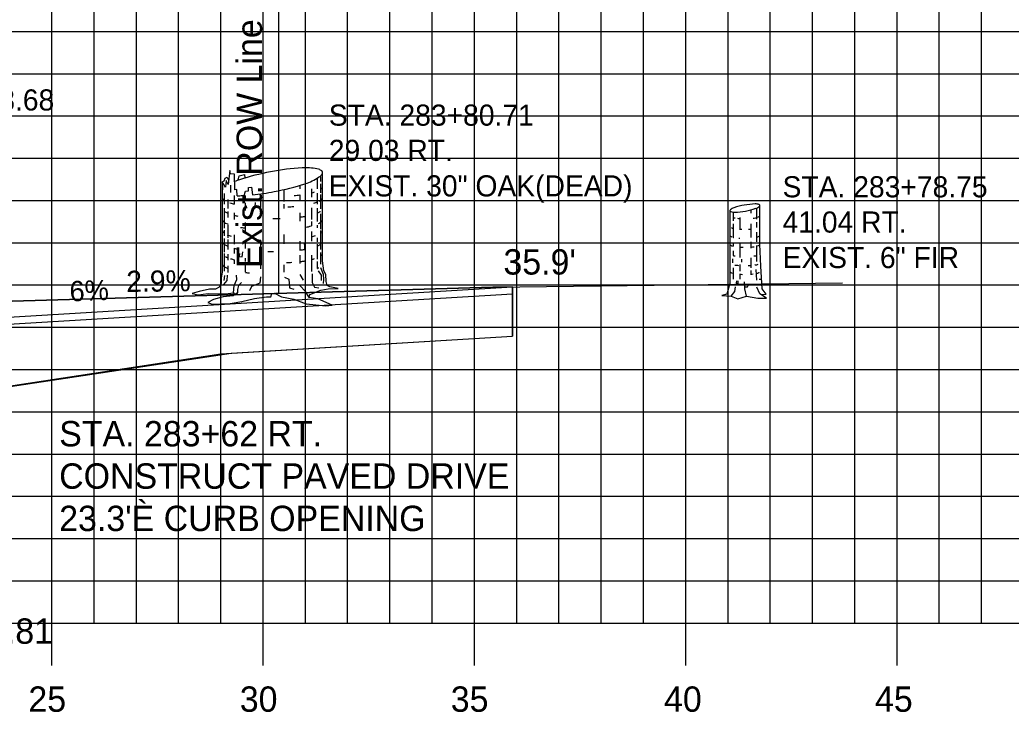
# Model space of a CAD drawing. Extents: x 856235 to 856405, y 366268 to 366378.
# Drawn here: x 856342.02 to 856365.48, y 366298.78 to 366315.17 of the extents above; entities that cross this region are included whole.
import ezdxf

# ---------------------------------------------------------------- set-up
doc = ezdxf.new("R2010")
doc.units = 0
for name, color, linetype in [('ANNOTATION', 7, 'Continuous'), ('D_Roadway_Drive_Gravel_RT', 7, 'Continuous'), ('D_Roadway_Drive_SubGrade', 7, 'Continuous'), ('D_Roadway_FinishedGrade', 7, 'Continuous'), ('D_Text_Monospaced', 7, 'Continuous'), ('D_Text_Standard', 7, 'Continuous'), ('E_ROW_Line', 7, 'Continuous'), ('H_V ANNOTATION', 7, 'Continuous'), ('JUNK COM EXC', 7, 'Continuous'), ('MAJOR', 7, 'Continuous'), ('MINOR', 7, 'Continuous'), ('S_Roadway_Centerline', 7, 'Continuous'), ('S_Trees_Conifer_NonPay', 7, 'Continuous'), ('S_Trees_Decid_Pay', 7, 'Continuous')]:
    doc.layers.add(name, color=color, linetype=linetype)

msp = doc.modelspace()

# ---------------------------------------------------------------- linework, layer by layer
at = {"layer": 'D_Roadway_Drive_Gravel_RT'}
for p, q in [((856340.78, 366308.074), (856353.683, 366308.849)), ((856340.79, 366307.908), (856353.683, 366308.682))]:
    msp.add_line(p, q, dxfattribs=at)
at = {"layer": 'D_Roadway_Drive_SubGrade'}
for p, q in [((856353.683, 366308.849), (856353.683, 366307.682)), ((856335.78, 366305.586), (856346.781, 366307.266))]:
    msp.add_line(p, q, dxfattribs=at)
at = {"layer": 'D_Roadway_FinishedGrade'}
msp.add_line((856346.781, 366307.266), (856353.683, 366307.68), dxfattribs=at)
at = {"layer": 'E_ROW_Line'}
msp.add_line((856348.153, 366308.696), (856348.153, 366318.696), dxfattribs=at)
at = {"layer": 'JUNK COM EXC'}
msp.add_lwpolyline([(856335.781, 366308.158), (856335.781, 366305.586), (856347.021, 366307.28), (856353.683, 366307.68), (856353.683, 366308.849), (856353.214, 366308.843), (856341.841, 366308.513), (856336.902, 366308.157), (856335.781, 366308.158)], dxfattribs=at)
at = {"layer": 'MAJOR'}
for p, q in [((856342.781, 366300.893), (856342.781, 366315.893)), ((856347.781, 366300.893), (856347.781, 366315.893)), ((856352.781, 366300.893), (856352.781, 366315.893)), ((856357.781, 366300.893), (856357.781, 366315.893)), ((856362.781, 366300.893), (856362.781, 366315.893)), ((856247.781, 366310.893), (856387.781, 366310.893)), ((856247.781, 366305.893), (856387.781, 366305.893)), ((856247.781, 366300.893), (856387.781, 366300.893)), ((856247.781, 366300.893), (856387.781, 366300.893)), ((856342.781, 366299.891), (856342.781, 366300.893)), ((856347.781, 366299.891), (856347.781, 366300.893)), ((856352.781, 366299.891), (856352.781, 366300.893)), ((856357.781, 366299.891), (856357.781, 366300.893)), ((856362.781, 366299.891), (856362.781, 366300.893))]:
    msp.add_line(p, q, dxfattribs=at)
at = {"layer": 'MINOR'}
for p, q in [((856343.781, 366300.893), (856343.781, 366315.893)), ((856344.781, 366300.893), (856344.781, 366315.893)), ((856345.781, 366300.893), (856345.781, 366315.893)), ((856346.781, 366300.893), (856346.781, 366315.893)), ((856348.781, 366300.893), (856348.781, 366315.893)), ((856349.781, 366300.893), (856349.781, 366315.893)), ((856350.781, 366300.893), (856350.781, 366315.893)), ((856351.781, 366300.893), (856351.781, 366315.893)), ((856353.781, 366300.893), (856353.781, 366315.893)), ((856354.781, 366300.893), (856354.781, 366315.893)), ((856355.781, 366300.893), (856355.781, 366315.893)), ((856356.781, 366300.893), (856356.781, 366315.893)), ((856358.781, 366300.893), (856358.781, 366315.893)), ((856359.781, 366300.893), (856359.781, 366315.893)), ((856360.781, 366300.893), (856360.781, 366315.893)), ((856361.781, 366300.893), (856361.781, 366315.893)), ((856363.781, 366300.893), (856363.781, 366315.893)), ((856364.781, 366300.893), (856364.781, 366315.893)), ((856247.781, 366314.893), (856387.781, 366314.893)), ((856247.781, 366313.893), (856387.781, 366313.893)), ((856247.781, 366312.893), (856387.781, 366312.893)), ((856247.781, 366311.893), (856387.781, 366311.893)), ((856247.781, 366309.893), (856387.781, 366309.893)), ((856247.781, 366308.893), (856387.781, 366308.893)), ((856247.781, 366307.893), (856387.781, 366307.893)), ((856247.781, 366306.893), (856387.781, 366306.893)), ((856247.781, 366304.893), (856387.781, 366304.893)), ((856247.781, 366303.893), (856387.781, 366303.893)), ((856247.781, 366302.893), (856387.781, 366302.893)), ((856247.781, 366301.893), (856387.781, 366301.893))]:
    msp.add_line(p, q, dxfattribs=at)
at = {"layer": 'S_Roadway_Centerline'}
msp.add_lwpolyline([(856288.766, 366307.134), (856291.997, 366307.346), (856293.116, 366307.459), (856296.849, 366307.753), (856299.153, 366307.782), (856300.226, 366307.769), (856300.611, 366307.582), (856300.668, 366307.591), (856300.837, 366307.587), (856302.732, 366307.68), (856307.504, 366307.852), (856314.412, 366308.118), (856317.731, 366308.235), (856325.349, 366308.101), (856328.588, 366308.036), (856330.64, 366308.017), (856333.315, 366308.002), (856333.411, 366308.015), (856334.63, 366308.158), (856336.902, 366308.157), (856341.841, 366308.513), (856353.214, 366308.843), (856361.49, 366308.945)], dxfattribs=at)
at = {"layer": 'S_Trees_Conifer_NonPay'}
for p, q in [((856358.903, 366310.616), (856358.903, 366310.411)), ((856359.321, 366310.671), (856359.321, 366310.593)), ((856358.903, 366310.338), (856358.903, 366310.007)), ((856359.06, 366310.491), (856359.06, 366310.218)), ((856359.321, 366310.343), (856359.321, 366310.018)), ((856359.456, 366310.383), (856359.456, 366310.252)), ((856359.456, 366310.143), (856359.456, 366309.917)), ((856358.903, 366309.892), (856358.903, 366309.814)), ((856359.06, 366309.864), (856359.06, 366309.546)), ((856359.321, 366309.917), (856359.321, 366309.763)), ((856359.456, 366309.825), (856359.456, 366309.449)), ((856358.903, 366309.7), (856358.903, 366309.59)), ((856358.886, 366309.512), (856358.886, 366309.415)), ((856359.06, 366309.376), (856359.06, 366309.217)), ((856359.101, 366309.501), (856359.101, 366309.432)), ((856359.321, 366309.535), (856359.321, 366309.301)), ((856358.903, 366309.301), (856358.903, 366309.033)), ((856359.06, 366309.159), (856359.06, 366309.028)), ((856359.321, 366309.239), (856359.321, 366309.153)), ((856359.437, 366309.256), (856359.455, 366309.011)), ((856359.516, 366309.028), (856359.577, 366309.034))]:
    msp.add_line(p, q, dxfattribs=at)
for points in [[(856359.567, 366308.667), (856359.683, 366308.676), (856359.591, 366308.801), (856359.558, 366309.342), (856359.537, 366309.859), (856359.537, 366310.778)], [(856358.824, 366310.65), (856358.824, 366308.932), (856358.754, 366308.676), (856358.635, 366308.642), (856358.852, 366308.625), (856359.011, 366308.567), (856359.22, 366308.625), (856359.483, 366308.578), (856359.689, 366308.584), (856359.537, 366308.687), (856359.466, 366308.841)], [(856359.456, 366310.712), (856359.456, 366310.615), (856359.456, 366310.45)], [(856358.983, 366308.988), (856358.972, 366308.944), (856359.022, 366308.932), (856359.022, 366308.994)], [(856359.22, 366308.625), (856359.176, 366308.801), (856359.17, 366308.966)], [(856359.174, 366308.851), (856359.243, 366308.846), (856359.262, 366308.898)], [(856358.852, 366308.625), (856358.941, 366308.738), (856358.958, 366308.852)]]:
    msp.add_lwpolyline(points, dxfattribs=at)
for centre, radius, start, end in [((856359.496, 366308.988), 1.825, 100.3798, 108.3946), ((856359.496, 366308.988), 1.825, 92.3651, 100.3798), ((856359.431, 366310.567), 0.245, 70.3798, 92.3651), ((856359.363, 366310.939), 0.245, 288.3946, 310.3798), ((856359.489, 366310.729), 0.0729, 59.1402, 70.3798), ((856359.475, 366310.808), 0.0729, 310.3798, 321.6195), ((856359.513, 366310.769), 0.0263, 40.3798, 59.1402), ((856359.511, 366310.779), 0.0263, 321.6195, 340.3798), ((856359.519, 366310.774), 0.0186, 26.433, 40.3798), ((856359.523, 366310.776), 0.0141, 10.3798, 26.433), ((856359.518, 366310.776), 0.0186, 340.3798, 354.3267), ((856359.523, 366310.776), 0.0141, 354.3267, 10.3798), ((856358.842, 366310.65), 0.0186, 160.3798, 174.3267), ((856358.838, 366310.65), 0.0141, 174.3267, 190.3798), ((856358.838, 366310.65), 0.0141, 190.3798, 206.433), ((856358.839, 366310.535), 0.0143, 180, 196.0515), ((856358.85, 366310.647), 0.0263, 141.6195, 160.3798), ((856358.842, 366310.652), 0.0186, 206.433, 220.3798), ((856358.848, 366310.657), 0.0263, 220.3798, 239.1402), ((856358.886, 366310.618), 0.0729, 130.3798, 141.6195), ((856358.872, 366310.697), 0.0729, 239.1402, 250.3798), ((856358.998, 366310.487), 0.245, 108.3946, 130.3798), ((856358.93, 366310.86), 0.245, 250.3798, 272.3651), ((856358.864, 366312.439), 1.825, 272.3651, 280.3798), ((856358.864, 366312.439), 1.825, 280.3798, 288.3946), ((856359.396, 366310.723), 0.245, 291.7653, 300), ((856359.481, 366310.575), 0.0738, 300, 311.2506), ((856359.512, 366310.54), 0.0267, 311.2506, 330), ((856359.519, 366310.536), 0.0189, 330, 343.9485), ((856358.966, 366310.723), 0.245, 254.8461, 261.8968), ((856359.181, 366312.231), 1.767, 261.8968, 262.605), ((856359.181, 366312.231), 1.767, 264.3267, 266.0499), ((856359.181, 366312.231), 1.767, 276.2449, 278.1032), ((856359.396, 366310.723), 0.245, 278.1032, 284.1859), ((856359.514, 366310.288), 0.0267, 311.2506, 330), ((856359.521, 366310.284), 0.0189, 330, 343.9485), ((856358.839, 366310.069), 0.0143, 180, 196.0515), ((856358.843, 366310.07), 0.0189, 196.0515, 210), ((856358.85, 366310.074), 0.0267, 210, 228.7494), ((856358.881, 366310.109), 0.0738, 228.7494, 240), ((856358.966, 366310.257), 0.245, 240, 246.7914), ((856358.968, 366310.471), 0.245, 244.3148, 257.5375), ((856359.183, 366311.978), 1.767, 265.8991, 267.5962), ((856359.183, 366311.978), 1.767, 272.7221, 274.4847), ((856359.396, 366310.257), 0.245, 284.1859, 300), ((856359.481, 366310.109), 0.0738, 300, 311.2506), ((856359.512, 366310.074), 0.0267, 311.2506, 330), ((856359.519, 366310.07), 0.0189, 330, 343.9485), ((856358.839, 366309.857), 0.0143, 180, 196.0515), ((856358.843, 366309.858), 0.0189, 196.0515, 210), ((856358.85, 366309.862), 0.0267, 210, 228.7494), ((856358.881, 366309.898), 0.0738, 228.7494, 240), ((856358.967, 366310.046), 0.245, 240, 254.9514), ((856358.966, 366310.257), 0.245, 254.8461, 257.5454), ((856359.181, 366311.765), 1.767, 265.2285, 266.1325), ((856359.181, 366311.553), 1.767, 274.5361, 277.0026), ((856359.396, 366310.046), 0.245, 292.1924, 300), ((856359.481, 366309.898), 0.0738, 300, 311.2506), ((856359.512, 366309.862), 0.0267, 311.2506, 330), ((856359.519, 366309.858), 0.0189, 330, 343.9485), ((856358.966, 366309.826), 0.245, 254.9814, 261.8968), ((856359.18, 366311.334), 1.767, 261.8968, 262.45), ((856359.181, 366311.553), 1.767, 266.0429, 268.5525), ((856359.18, 366311.334), 1.767, 276.7966, 278.1032), ((856359.395, 366309.826), 0.245, 278.1032, 284.3207), ((856358.838, 366309.421), 0.0143, 180, 196.0515), ((856359.18, 366311.117), 1.767, 262.2622, 265.0496), ((856359.18, 366311.117), 1.767, 272.6293, 274.5612), ((856359.18, 366311.117), 1.767, 277.63, 278.1032), ((856359.395, 366309.609), 0.245, 278.1032, 294.6056), ((856358.838, 366309.215), 0.0143, 180, 196.0515), ((856358.842, 366309.216), 0.0189, 196.0515, 210), ((856358.849, 366309.22), 0.0267, 210, 228.7494), ((856358.88, 366309.256), 0.0738, 228.7494, 240), ((856358.965, 366309.403), 0.245, 240, 249.1675), ((856359.18, 366310.911), 1.767, 266.0862, 268.2187), ((856359.18, 366310.911), 1.767, 274.2776, 276.3006), ((856359.395, 366309.403), 0.245, 284.0684, 300), ((856359.48, 366309.256), 0.0738, 300, 302.05)]:
    msp.add_arc(centre, radius, start, end, dxfattribs=at)
at = {"layer": 'S_Trees_Decid_Pay'}
for p, q in [((856349.137, 366311.463), (856349.137, 366311.342)), ((856347.012, 366311.259), (856347.012, 366311.085)), ((856348.652, 366311.252), (856348.652, 366311.165)), ((856349.056, 366311.418), (856349.056, 366311.165)), ((856349.137, 366311.29), (856349.137, 366311.076)), ((856346.862, 366311.059), (856346.862, 366310.805)), ((856347.097, 366311.011), (856347.097, 366310.806)), ((856347.358, 366311.013), (856347.358, 366310.893)), ((856348.268, 366311.151), (856348.268, 366310.87)), ((856348.652, 366311.024), (856348.652, 366310.885)), ((856348.924, 366311.165), (856348.924, 366310.973)), ((856349.056, 366311.069), (856349.056, 366310.805)), ((856349.137, 366311.031), (856349.137, 366310.693)), ((856346.948, 366310.914), (856346.948, 366310.702)), ((856347.358, 366310.841), (856347.358, 366310.656)), ((856347.596, 366310.741), (856347.601, 366310.848)), ((856347.722, 366310.914), (856347.722, 366310.734)), ((856348.268, 366310.805), (856348.268, 366310.702)), ((856346.862, 366310.708), (856346.862, 366310.238)), ((856346.948, 366310.636), (856346.948, 366310.488)), ((856347.097, 366310.599), (856347.097, 366310.445)), ((856348.652, 366310.599), (856348.652, 366310.407)), ((856348.924, 366310.722), (856348.924, 366310.445)), ((856349.056, 366310.708), (856349.056, 366310.399)), ((856349.137, 366310.576), (856349.137, 366310.216)), ((856346.948, 366310.311), (856346.948, 366310.01)), ((856347.358, 366310.37), (856347.358, 366310.142)), ((856348.924, 366310.399), (856348.924, 366310.29)), ((856349.056, 366310.311), (856349.056, 366310.244)), ((856346.862, 366310.187), (856346.862, 366310.053)), ((856347.097, 366310.082), (856347.097, 366309.862)), ((856348.268, 366310.09), (856348.268, 366309.87)), ((856348.924, 366310.156), (856348.924, 366309.927)), ((856349.137, 366310.179), (856349.137, 366309.73)), ((856346.862, 366309.996), (856346.862, 366309.67)), ((856346.948, 366309.973), (856346.948, 366309.73)), ((856347.358, 366309.944), (856347.358, 366309.759)), ((856347.722, 366309.956), (856347.722, 366309.759)), ((856348.652, 366309.927), (856348.652, 366309.719)), ((856349.056, 366310.01), (856349.056, 366309.913)), ((856349.056, 366309.862), (856349.056, 366309.502)), ((856346.862, 366309.641), (856346.862, 366309.221)), ((856346.948, 366309.619), (856346.948, 366309.479)), ((856347.097, 366309.762), (856347.097, 366309.641)), ((856348.652, 366309.598), (856348.652, 366309.399)), ((856348.924, 366309.598), (856348.924, 366309.215)), ((856349.137, 366309.664), (856349.137, 366309.382)), ((856346.948, 366309.347), (856346.948, 366309.191)), ((856347.097, 366309.49), (856347.097, 366309.392)), ((856347.358, 366309.524), (856347.358, 366309.447)), ((856347.358, 366309.37), (856347.358, 366309.196)), ((856347.722, 366309.376), (856347.722, 366309.273)), ((856348.268, 366309.37), (856348.268, 366309.196)), ((856349.056, 366309.45), (856349.056, 366309.283)), ((856346.866, 366309.118), (856346.851, 366309.001)), ((856348.647, 366309.141), (856348.727, 366309.009))]:
    msp.add_line(p, q, dxfattribs=at)
for points in [[(856346.812, 366311.334), (856346.812, 366309.196), (856346.791, 366309.055), (856346.785, 366308.929), (856346.742, 366308.842), (856346.65, 366308.793), (856346.514, 366308.793), (856346.27, 366308.737), (856346.104, 366308.688), (856346.246, 366308.657), (856346.483, 366308.695), (856346.693, 366308.682), (856346.954, 366308.688), (856347.078, 366308.706), (856347.108, 366308.664), (856347.171, 366308.706), (856347.072, 366308.639), (856346.837, 366308.614), (856346.606, 366308.552), (856346.476, 366308.482), (856346.576, 366308.439), (856346.997, 366308.458), (856347.276, 366308.501), (856347.574, 366308.577), (856347.86, 366308.614), (856347.965, 366308.614), (856347.984, 366308.695), (856348.052, 366308.7), (856348.219, 366308.614), (856348.505, 366308.558), (856348.803, 366308.451), (856349.263, 366308.402), (856349.417, 366308.414), (856349.075, 366308.565), (856348.871, 366308.595), (856348.883, 366308.67), (856349.143, 366308.769), (856349.318, 366308.8), (856349.559, 366308.811), (856349.361, 366308.849), (856349.299, 366308.885), (856349.275, 366308.972), (856349.263, 366309.141), (856349.217, 366309.227), (856349.189, 366309.468), (856349.189, 366311.554)], [(856347.168, 366311.006), (856347.16, 366311.151), (856347.115, 366311.143), (856347.1, 366311.517), (856347.006, 366311.525), (856346.992, 366311.605), (856346.954, 366311.268), (856346.909, 366311.362), (856346.888, 366311.208), (856346.812, 366311.334), (856346.818, 366311.144)], [(856346.812, 366311.334), (856346.858, 366311.357), (856346.88, 366311.422), (856346.932, 366311.445), (856346.965, 366311.37)], [(856347.19, 366311.372), (856347.211, 366311.48), (856347.343, 366311.511), (856347.35, 366311.423)], [(856347.329, 366311.011), (856347.366, 366311.114), (856347.432, 366311.12), (856347.432, 366311.202), (856347.506, 366311.208), (856347.531, 366311.028)], [(856348.765, 366309.733), (856348.764, 366309.81), (856348.756, 366309.876)], [(856347.22, 366309.641), (856347.211, 366309.567), (856347.285, 366309.561), (856347.3, 366309.678)], [(856346.932, 366309.126), (856346.925, 366309.001), (856346.843, 366308.906)], [(856347.078, 366308.706), (856347.097, 366308.885), (856347.158, 366309.022), (856347.152, 366309.122)], [(856347.721, 366309.09), (856347.703, 366308.935), (856347.506, 366308.855), (856347.461, 366308.752)], [(856348.941, 366309.155), (856348.941, 366308.95), (856348.999, 366308.84), (856349.096, 366308.824)], [(856349.081, 366309.229), (856349.153, 366309.126), (856349.153, 366309.001)], [(856349.138, 366309.31), (856349.199, 366309.149), (856349.213, 366309.024), (856349.205, 366308.927)], [(856347.269, 366308.954), (856347.195, 366308.885), (856347.177, 366308.787), (856347.171, 366308.706)], [(856348.286, 366309.081), (856348.389, 366309.03), (856348.404, 366308.824), (856348.507, 366308.795)], [(856348.871, 366308.595), (856348.785, 366308.737), (856348.653, 366308.88)]]:
    msp.add_lwpolyline(points, dxfattribs=at)
for centre, radius, start, end in [((856348.791, 366310.369), 1.299, 78.2779, 93.6944), ((856349.102, 366305.553), 6.126, 100.7779, 107.8613), ((856349.102, 366305.553), 6.126, 93.6944, 100.7779), ((856348.38, 366312.528), 1.299, 287.8613, 303.2779), ((856348.957, 366311.172), 0.48, 69.9843, 78.2779), ((856348.83, 366311.842), 0.48, 303.2779, 311.5714), ((856349.065, 366311.468), 0.164, 55.7779, 69.9843), ((856349.039, 366311.606), 0.164, 311.5714, 325.7779), ((856349.097, 366311.515), 0.107, 45.9547, 55.7779), ((856349.127, 366311.546), 0.0645, 33.2779, 45.9547), ((856349.086, 366311.574), 0.107, 325.7779, 335.6011), ((856349.135, 366311.551), 0.0544, 22.46, 33.2779), ((856349.125, 366311.556), 0.0645, 335.6011, 348.2779), ((856349.142, 366311.554), 0.0467, 10.7779, 22.46), ((856349.142, 366311.554), 0.0467, 359.0957, 10.7779), ((856349.135, 366311.554), 0.0544, 348.2779, 359.0957), ((856347.621, 366310.146), 1.299, 107.8613, 113.3069), ((856346.899, 366317.121), 6.126, 280.7779, 287.8613), ((856349.125, 366311.232), 0.0657, 324.8263, 337.5), ((856349.135, 366311.228), 0.0554, 337.5, 348.3185), ((856346.86, 366310.965), 0.0476, 180, 191.6815), ((856347.21, 366312.305), 1.299, 268.1289, 273.6944), ((856346.899, 366317.121), 6.126, 273.6944, 274.0246), ((856346.899, 366317.121), 6.126, 275.9147, 280.7779), ((856348.002, 366316.904), 5.916, 274.9515, 276.3087), ((856348.577, 366312.316), 1.292, 285.5651, 289.0916), ((856349.049, 366311.297), 0.166, 301.67, 315), ((856349.09, 366311.257), 0.109, 315, 324.8263), ((856346.867, 366310.967), 0.0554, 191.6815, 202.5), ((856346.877, 366310.971), 0.0657, 202.5, 215.1737), ((856346.912, 366310.996), 0.109, 215.1737, 225), ((856346.953, 366311.036), 0.166, 225, 239.1924), ((856347.425, 366312.056), 1.292, 250.6119, 255.2856), ((856348.001, 366316.644), 5.916, 266.0776, 267.3043), ((856348.001, 366316.644), 5.916, 273.5382, 274.8924), ((856348.576, 366312.056), 1.292, 288.0829, 292.5), ((856348.886, 366311.309), 0.484, 297.4162, 300.8076), ((856349.048, 366311.036), 0.166, 300.8076, 315), ((856349.089, 366310.996), 0.109, 315, 324.8263), ((856349.124, 366310.971), 0.0657, 324.8263, 337.5), ((856349.134, 366310.967), 0.0554, 337.5, 348.3185), ((856346.953, 366310.773), 0.166, 237.0378, 239.1924), ((856347.116, 366311.046), 0.484, 239.1924, 247.5), ((856347.425, 366311.792), 1.292, 247.5, 248.3537), ((856347.425, 366311.792), 1.292, 255.2856, 259.2632), ((856348.001, 366316.38), 5.916, 276.3184, 277.1546), ((856348.576, 366311.792), 1.292, 277.1546, 278.3662), ((856348.576, 366311.792), 1.292, 291.8071, 292.5), ((856348.886, 366311.046), 0.484, 292.5, 300.8076), ((856349.048, 366310.773), 0.166, 300.8076, 301.6001), ((856346.86, 366310.444), 0.0476, 180, 191.6815), ((856346.867, 366310.446), 0.0554, 191.6815, 202.5), ((856346.877, 366310.45), 0.0657, 202.5, 215.1737), ((856346.912, 366310.475), 0.109, 215.1737, 225), ((856346.953, 366310.515), 0.166, 225, 239.1924), ((856347.116, 366310.788), 0.484, 239.1924, 245.7725), ((856347.425, 366311.535), 1.292, 247.5, 248.4842), ((856348.001, 366316.38), 5.916, 270.1162, 271.7708), ((856348.576, 366311.535), 1.292, 279.2565, 285.6105), ((856348.886, 366310.788), 0.484, 294.6372, 300.8076), ((856349.048, 366310.515), 0.166, 300.8076, 315), ((856349.089, 366310.475), 0.109, 315, 324.8263), ((856349.124, 366310.45), 0.0657, 324.8263, 337.5), ((856349.134, 366310.446), 0.0554, 337.5, 348.3185), ((856346.86, 366310.187), 0.0476, 180, 191.6815), ((856346.867, 366310.189), 0.0554, 191.6815, 202.5), ((856346.877, 366310.192), 0.0657, 202.5, 215.1737), ((856346.912, 366310.217), 0.109, 215.1737, 225), ((856346.953, 366310.258), 0.166, 225, 239.1924), ((856347.425, 366311.277), 1.292, 247.5, 251.799), ((856347.425, 366311.535), 1.292, 261.8726, 262.8454), ((856348.001, 366316.123), 5.916, 262.8454, 263.7595), ((856348.576, 366311.277), 1.292, 285.6105, 290.1001), ((856349.048, 366310.258), 0.166, 302.0694, 315), ((856349.089, 366310.217), 0.109, 315, 324.8263), ((856349.124, 366310.192), 0.0657, 324.8263, 337.5), ((856349.134, 366310.189), 0.0554, 337.5, 348.3185), ((856346.86, 366309.921), 0.0476, 180, 191.6815), ((856346.867, 366309.923), 0.0554, 191.6815, 202.5), ((856346.877, 366309.927), 0.0657, 202.5, 215.1737), ((856346.912, 366309.952), 0.109, 215.1737, 225), ((856346.953, 366309.992), 0.166, 225, 239.1924), ((856347.116, 366310.265), 0.484, 239.1924, 247.5), ((856347.425, 366311.012), 1.292, 247.5, 248.3537), ((856348.001, 366315.865), 5.916, 266.2721, 267.3043), ((856348.886, 366310.265), 0.484, 292.5, 300.8076), ((856349.048, 366309.992), 0.166, 300.8076, 302.0694), ((856349.134, 366309.923), 0.0554, 337.5, 348.3185), ((856347.116, 366309.994), 0.484, 242.734, 247.5), ((856347.425, 366311.012), 1.292, 255.2856, 259.2463), ((856348.001, 366315.6), 5.916, 268.9207, 270), ((856348.001, 366315.6), 5.916, 270, 270.2757), ((856348.001, 366315.6), 5.916, 276.3184, 277.1546), ((856348.576, 366311.012), 1.292, 277.1546, 278.3795), ((856349.048, 366309.721), 0.166, 302.0694, 315), ((856349.089, 366309.68), 0.109, 315, 324.8263), ((856349.124, 366309.655), 0.0657, 324.8263, 337.5), ((856349.134, 366309.651), 0.0554, 337.5, 348.3185), ((856346.86, 366309.392), 0.0476, 180, 191.6815), ((856346.867, 366309.394), 0.0554, 191.6815, 202.5), ((856346.877, 366309.398), 0.0657, 202.5, 215.1737), ((856346.912, 366309.423), 0.109, 215.1737, 225), ((856346.953, 366309.463), 0.166, 225, 239.1924), ((856347.425, 366310.74), 1.292, 251.3664, 255.2856), ((856348.001, 366315.328), 5.916, 273.2637, 274.461), ((856348.001, 366315.328), 5.916, 276.3184, 277.1546), ((856348.576, 366310.74), 1.292, 277.1546, 278.3662), ((856348.576, 366310.74), 1.292, 285.6105, 289.1534), ((856347.116, 366309.736), 0.484, 239.1924, 247.5), ((856347.425, 366310.483), 1.292, 247.5, 248.3537), ((856348.001, 366315.07), 5.916, 263.7831, 264.7656), ((856348.586, 366310.486), 1.292, 291.3696, 292.0604), ((856348.886, 366309.736), 0.484, 292.5, 296.5499)]:
    msp.add_arc(centre, radius, start, end, dxfattribs=at)

# ---------------------------------------------------------------- texts
at = {"layer": 'ANNOTATION'}
for s, p in [('STA. 283+62 RT.', (856342.955, 366305.074)), ('CONSTRUCT PAVED DRIVE', (856342.955, 366304.072)), ("23.3'È CURB OPENING", (856342.955, 366303.07))]:
    msp.add_text(s, height=0.6, dxfattribs=at).set_placement(p)
at = {"layer": 'D_Roadway_Drive_Gravel_RT'}
msp.add_text('6%', height=0.48, rotation=2.2906, dxfattribs=at).set_placement((856343.21, 366308.503))
at = {"layer": 'D_Text_Monospaced'}
for s, height, p in [('STA. 283+78.68', 0.49998, (856337.988, 366313.022)), ('STA. 283+80.71', 0.49998, (856349.335, 366312.663)), ('29.03 RT.', 0.5, (856349.335, 366311.829)), ('EXIST. 30" OAK(DEAD)', 0.49998, (856349.335, 366310.989)), ('STA. 283+78.75', 0.49998, (856360.072, 366310.967)), ('41.04 RT.', 0.5, (856360.072, 366310.133)), ('EXIST. 6" FIR', 0.49998, (856360.072, 366309.293))]:
    msp.add_text(s, height=height, dxfattribs=at).set_placement(p)
msp.add_text('2.9%', height=0.5, rotation=0.6756, dxfattribs=at).set_placement((856344.545, 366308.728))
at = {"layer": 'D_Text_Standard'}
for s, p in [("35.9'", (856353.467, 366309.14)), ('ELEV. = 254.81', (856337.166, 366300.403))]:
    msp.add_text(s, height=0.6, dxfattribs=at).set_placement(p)
at = {"layer": 'E_ROW_Line'}
msp.add_text('Exist. ROW Line', height=0.6, rotation=90, dxfattribs=at).set_placement((856347.753, 366309.296))
at = {"layer": 'H_V ANNOTATION'}
for s, p in [('25', (856342.227, 366298.793)), ('30', (856347.229, 366298.793)), ('35', (856352.221, 366298.793)), ('40', (856357.267, 366298.793)), ('45', (856362.259, 366298.793))]:
    msp.add_text(s, height=0.6, dxfattribs=at).set_placement(p)

doc.saveas('drawing.dxf')
